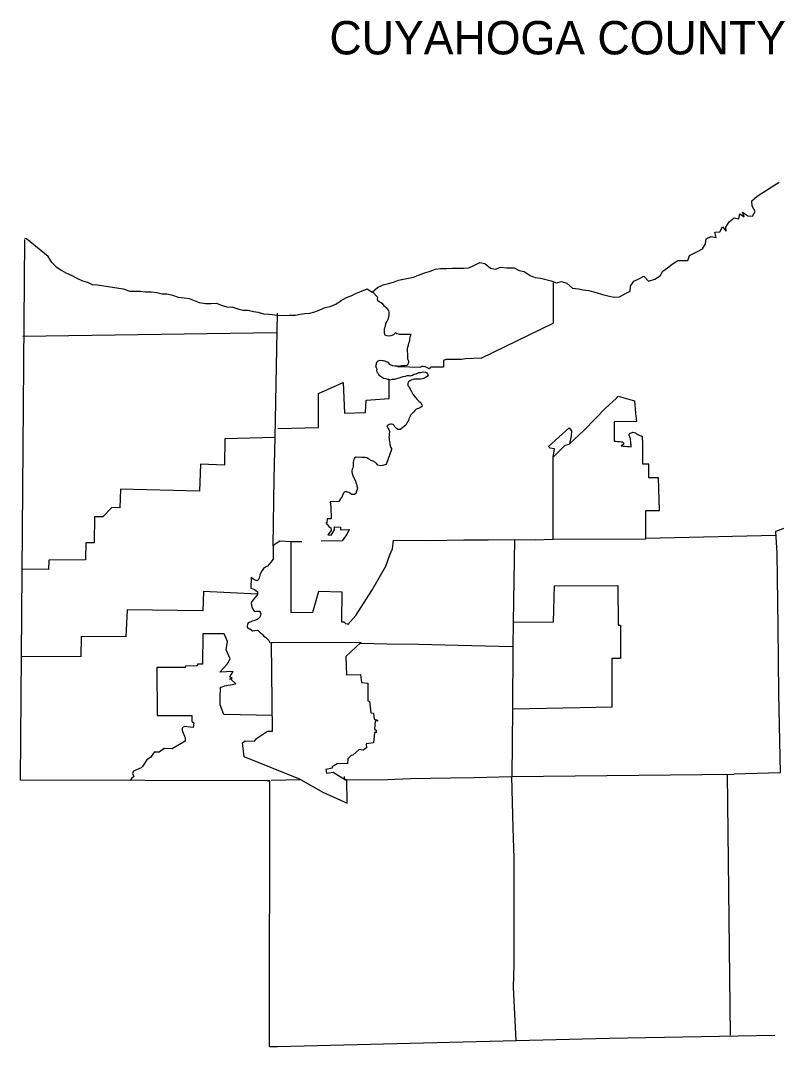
# Model space of a CAD drawing. Extents: x 0 to 42.4, y 0 to 22.
# Drawn here: x 35.55 to 38.719, y 8.263 to 12.563 of the extents above; entities that cross this region are included whole.
import ezdxf

# ---------------------------------------------------------------- set-up
doc = ezdxf.new("R2010")
doc.units = 0
doc.layers.add('Default', color=7, linetype='Continuous')

msp = doc.modelspace()

# ---------------------------------------------------------------- linework, layer by layer
at = {"layer": 'Default'}
for p, q in [((35.55, 9.3795), (35.5675, 11.6444)), ((37.4812, 11.147), (37.7829, 11.2937)), ((38.0562, 10.9878), (38.124, 10.9686)), ((37.833, 10.7825), (37.7837, 10.7319)), ((36.5953, 9.3761), (35.55, 9.3795)), ((36.594, 8.2627), (36.5953, 9.3761))]:
    msp.add_line(p, q, dxfattribs=at)
for points in [[(38.3887, 11.5947), (38.4088, 11.6057), (38.4221, 11.626), (38.4243, 11.6475), (38.4455, 11.6573), (38.4663, 11.6535), (38.4615, 11.675), (38.4821, 11.6773), (38.4937, 11.6981), (38.5078, 11.6792), (38.5073, 11.6969), (38.5203, 11.7186), (38.5415, 11.7355), (38.5622, 11.7317), (38.5651, 11.7518), (38.5837, 11.7394), (38.5764, 11.7599), (38.5997, 11.7444), (38.6193, 11.7427), (38.6305, 11.7625), (38.6178, 11.7838), (38.6159, 11.8067), (38.6388, 11.826), (38.662, 11.8418), (38.6847, 11.8551), (38.7088, 11.8714), (38.7308, 11.8847)], [(35.666, 11.5733), (35.5744, 11.6475), (35.5686, 11.6494)], [(35.6641, 11.5735), (35.6791, 11.5516), (35.6995, 11.5296), (35.7228, 11.5152), (35.7434, 11.5043), (35.7646, 11.4935), (35.7868, 11.4826), (35.8097, 11.4713), (35.831, 11.4665), (35.851, 11.4566), (35.8722, 11.4554), (35.9804, 11.4375)], [(37.9906, 11.4143), (38.0119, 11.4093), (38.0388, 11.4031), (38.0608, 11.4052), (38.0829, 11.4177), (38.1057, 11.4286), (38.108, 11.4494), (38.1211, 11.4702), (38.1429, 11.48), (38.1634, 11.4907), (38.1832, 11.4708), (38.209, 11.4782), (38.2312, 11.4926), (38.2426, 11.5124), (38.2627, 11.5265), (38.2827, 11.5417), (38.3062, 11.5568), (38.3257, 11.5568), (38.3472, 11.5565), (38.355, 11.5773), (38.3887, 11.5947), (38.3887, 11.5947)], [(36.6045, 11.331), (36.6272, 11.3283), (36.6504, 11.3267), (36.6768, 11.3283), (36.7029, 11.3283), (36.7224, 11.3315), (36.7416, 11.3351), (36.7628, 11.3357), (36.7833, 11.3422), (36.8053, 11.3499), (36.8273, 11.3592), (36.8487, 11.3639), (36.8721, 11.374), (36.8945, 11.3885), (36.9163, 11.4012), (36.9384, 11.4102), (36.9587, 11.4195), (36.9793, 11.4277), (37.0031, 11.4384), (37.0239, 11.4246), (37.047, 11.4432), (37.0698, 11.4541), (37.0929, 11.4603), (37.1142, 11.4656), (37.1352, 11.4737), (37.1557, 11.4782), (37.1765, 11.4825), (37.1981, 11.4868), (37.2192, 11.4952), (37.2414, 11.5041), (37.2671, 11.5127), (37.2905, 11.5205), (37.3111, 11.5234), (37.3363, 11.5234), (37.3598, 11.5253), (37.3831, 11.5253), (37.408, 11.5253), (37.4301, 11.526), (37.45, 11.5365), (37.4755, 11.5485), (37.497, 11.5446), (37.5204, 11.5246), (37.5416, 11.5198), (37.5626, 11.5293), (37.5893, 11.526), (37.6199, 11.5262), (37.6405, 11.5153), (37.6619, 11.5103), (37.6865, 11.4945), (37.7077, 11.4849), (37.7306, 11.4825), (37.7524, 11.4768), (37.775, 11.4714), (37.7973, 11.463), (37.8183, 11.4687), (37.84, 11.4618), (37.8646, 11.4403), (37.8887, 11.4379), (37.9089, 11.4336), (37.9319, 11.4315), (37.9631, 11.4233), (37.9906, 11.4143)], [(37.7829, 11.463), (37.7829, 11.2937)], [(35.9804, 11.4375), (35.9839, 11.4367), (36.0085, 11.4286), (36.0314, 11.4286), (36.0527, 11.4277), (36.0735, 11.426), (36.098, 11.4257), (36.1212, 11.4233), (36.1432, 11.4177), (36.1635, 11.4177), (36.1869, 11.4112), (36.211, 11.4031), (36.2365, 11.4009), (36.2573, 11.3974), (36.2776, 11.3885), (36.299, 11.3807), (36.3251, 11.3763), (36.3477, 11.3771), (36.3716, 11.378), (36.3916, 11.3699), (36.4146, 11.362), (36.4396, 11.3613), (36.4608, 11.3549), (36.4838, 11.3491), (36.505, 11.3492), (36.5265, 11.3437), (36.547, 11.34), (36.569, 11.3338), (36.5904, 11.3315), (36.6045, 11.331)], [(37.1304, 11.1138), (37.1406, 11.1152), (37.1478, 11.1164), (37.155, 11.1164), (37.1631, 11.1162), (37.1693, 11.1181), (37.1738, 11.1216), (37.1765, 11.126), (37.1776, 11.1298), (37.1778, 11.1331), (37.1764, 11.1379), (37.1743, 11.1439), (37.1741, 11.1493), (37.1745, 11.1561), (37.1741, 11.1634), (37.1731, 11.179), (37.1731, 11.187), (37.1741, 11.194), (37.1764, 11.2016), (37.1783, 11.2116), (37.1815, 11.2205), (37.1821, 11.2272), (37.1836, 11.2355), (37.1853, 11.2415), (37.1874, 11.2465), (37.155, 11.2465), (37.1395, 11.2465), (37.128, 11.2496), (37.1216, 11.253), (37.1137, 11.2453), (37.1024, 11.2413), (37.0953, 11.2401), (37.0864, 11.241), (37.0788, 11.2443), (37.0753, 11.2524), (37.0753, 11.2598), (37.0755, 11.2689), (37.0769, 11.2754), (37.0797, 11.2818), (37.0814, 11.2925), (37.0853, 11.3004), (37.091, 11.3105), (37.0939, 11.3202), (37.0953, 11.331), (37.096, 11.3393), (37.0936, 11.3468), (37.0869, 11.3551), (37.0815, 11.3597), (37.0753, 11.3649), (37.0705, 11.3725), (37.0616, 11.379), (37.0535, 11.3842), (37.0487, 11.3878), (37.047, 11.3931), (37.048, 11.4014), (37.0263, 11.426)], [(36.6172, 10.8149), (36.6268, 11.3367)], [(36.6236, 11.2541), (35.5598, 11.2382)], [(37.4812, 11.147), (37.4161, 11.1444), (37.3991, 11.1419), (37.3419, 11.1424), (37.3326, 11.1419), (37.3232, 11.1379), (37.3232, 11.1097), (37.269, 11.1097), (37.2636, 11.1024), (37.2538, 11.108), (37.2462, 11.1107), (37.2375, 11.1121), (37.2323, 11.1121), (37.2247, 11.1081), (37.1371, 11.1107), (37.133, 11.1107), (37.1304, 11.1138), (37.1198, 11.1138), (37.1106, 11.1147), (37.1036, 11.1179), (37.0986, 11.1203), (37.0936, 11.1259), (37.0872, 11.1303), (37.0784, 11.1346), (37.0719, 11.1357), (37.0671, 11.1364), (37.0599, 11.1376), (37.0521, 11.1369), (37.048, 11.1346), (37.0445, 11.13), (37.0411, 11.1259), (37.0408, 11.1216), (37.0402, 11.1164), (37.0383, 11.1124), (37.0404, 11.1088), (37.043, 11.1055), (37.0432, 11.1004), (37.043, 11.0956), (37.0437, 11.0902), (37.0461, 11.0871), (37.048, 11.0839), (37.0506, 11.0796), (37.0535, 11.0746), (37.0578, 11.073), (37.0669, 11.0684), (37.0717, 11.0639), (37.0815, 11.0617), (37.0905, 11.0592), (37.0932, 11.0589), (37.101, 11.0567), (37.1101, 11.0589), (37.1191, 11.0598), (37.1275, 11.062), (37.137, 11.0648), (37.1464, 11.0684), (37.1549, 11.0701), (37.164, 11.0727), (37.1717, 11.0746), (37.1796, 11.0746), (37.1843, 11.0734), (37.1927, 11.0763), (37.1993, 11.0801), (37.2082, 11.0818), (37.2146, 11.0839), (37.2196, 11.0871), (37.2247, 11.0878), (37.2285, 11.0878), (37.2337, 11.0887), (37.2409, 11.0902), (37.2476, 11.0887), (37.253, 11.0861), (37.2566, 11.0818), (37.2586, 11.0763), (37.2566, 11.0715), (37.2507, 11.0672), (37.2437, 11.0639), (37.2356, 11.0613), (37.227, 11.0594), (37.2192, 11.0598), (37.2113, 11.0594), (37.202, 11.0591), (37.1946, 11.0584), (37.1876, 11.0553), (37.1821, 11.0518), (37.175, 11.0469), (37.1745, 11.0412), (37.1745, 11.0333), (37.1796, 11.0272), (37.1836, 11.0171), (37.1895, 11.0078), (37.1951, 10.9963), (37.2039, 10.9847), (37.2142, 10.9722)], [(36.6291, 10.8529), (36.7986, 10.8567), (36.7986, 10.9999), (36.9027, 11.046), (36.9079, 10.9169), (36.9964, 10.92), (36.9988, 10.9716), (37.096, 10.9784), (37.0957, 11.0584)], [(37.2142, 10.9722), (37.2213, 10.9661), (37.2256, 10.963), (37.2302, 10.9574), (37.233, 10.9522), (37.2333, 10.9469), (37.2309, 10.9431), (37.2273, 10.94), (37.2222, 10.9384), (37.2179, 10.9371), (37.2129, 10.9355), (37.2077, 10.9322), (37.2032, 10.9281), (37.1987, 10.9221), (37.1865, 10.9095), (37.1815, 10.9016), (37.1783, 10.8927), (37.1771, 10.8853), (37.1731, 10.8803), (37.1693, 10.8744), (37.165, 10.867), (37.1599, 10.8618), (37.1518, 10.8555), (37.1473, 10.8526), (37.142, 10.8488), (37.1316, 10.8481), (37.1258, 10.8526), (37.1198, 10.8598), (37.1163, 10.8653), (37.1118, 10.8691), (37.1055, 10.8708), (37.101, 10.8708), (37.0953, 10.8692), (37.0907, 10.8667), (37.0864, 10.8634), (37.0886, 10.8579), (37.0917, 10.8529), (37.0943, 10.8481), (37.0974, 10.8396), (37.0962, 10.8293), (37.0957, 10.8219), (37.0943, 10.8168), (37.0957, 10.8128), (37.0957, 10.8051), (37.0969, 10.7983), (37.0977, 10.7902), (37.0984, 10.787), (37.0993, 10.7798), (37.1024, 10.773), (37.1049, 10.7689), (37.1058, 10.7648), (37.0829, 10.7025), (37.0671, 10.6975), (37.059, 10.6966), (37.053, 10.6975), (37.0483, 10.6987), (37.0423, 10.7064), (37.0383, 10.7102), (37.0278, 10.7154), (37.0199, 10.719), (37.0105, 10.7243), (37.002, 10.7295), (36.9946, 10.7316), (36.9816, 10.7314), (36.9683, 10.7328), (36.9611, 10.7317), (36.9552, 10.7319), (36.9504, 10.7278), (36.9468, 10.7231), (36.9466, 10.7178), (36.9449, 10.7097), (36.9452, 10.7021), (36.9452, 10.6937), (36.943, 10.688), (36.9404, 10.6825), (36.939, 10.6768), (36.9396, 10.6717), (36.9408, 10.6638), (36.9439, 10.6555), (36.9495, 10.6433), (36.954, 10.6333), (36.9559, 10.6264), (36.9581, 10.6199), (36.9602, 10.6121), (36.9626, 10.604), (36.9607, 10.5975), (36.959, 10.5896), (36.9552, 10.5806), (36.9504, 10.5767), (36.9445, 10.5763), (36.9378, 10.5767), (36.9311, 10.581), (36.9258, 10.5849), (36.9179, 10.5866), (36.9115, 10.5866), (36.9067, 10.5849), (36.9027, 10.5806), (36.9007, 10.5758), (36.8991, 10.5682), (36.8946, 10.5619), (36.8852, 10.5469)], [(37.833, 10.7825), (37.85, 10.7873), (37.9128, 10.8458), (37.9591, 10.8932), (38.0006, 10.936), (38.0484, 10.9797), (38.0562, 10.9878)], [(38.124, 10.9686), (38.1285, 10.9161), (38.1329, 10.8822)], [(38.1329, 10.8822), (38.0384, 10.8813), (38.0384, 10.7997)], [(38.1329, 10.8808), (38.1329, 10.8822)], [(37.7837, 10.7319), (37.7891, 10.7677), (37.7708, 10.7698), (37.7638, 10.7775), (37.85, 10.8548), (37.8601, 10.8433), (37.8581, 10.8219), (37.8509, 10.7878)], [(36.6096, 10.3607), (36.6134, 10.6433), (36.6172, 10.8149), (36.4067, 10.8094), (36.4048, 10.6994), (36.3043, 10.7033), (36.3, 10.5901), (35.9694, 10.5984), (35.9665, 10.5206), (35.9333, 10.5216), (35.8945, 10.4829), (35.8596, 10.4829), (35.8584, 10.3731), (35.8245, 10.3739), (35.8231, 10.302), (35.6684, 10.3015), (35.6672, 10.2614), (35.5555, 10.2631)], [(38.716, 10.4046), (38.1717, 10.3915), (38.171, 10.5092), (38.2285, 10.5092), (38.2254, 10.6455), (38.1842, 10.6464), (38.1842, 10.7039), (38.1584, 10.7033), (38.1588, 10.7866), (38.157, 10.8185)], [(36.7301, 10.3782), (36.6831, 10.3777), (36.6826, 10.0817), (36.7755, 10.0827), (36.801, 10.1708), (36.8972, 10.1677), (36.8953, 10.0425), (36.906, 10.0419), (36.912, 10.0352), (36.9192, 10.0337), (36.926, 10.0344), (36.9225, 10.0316), (36.9559, 10.0683), (37.0227, 10.1733), (37.0822, 10.2762), (37.0982, 10.3232), (37.1096, 10.3485), (37.1136, 10.3851), (37.2538, 10.3832), (37.3369, 10.3851), (37.4087, 10.3861), (37.4383, 10.3861), (37.5104, 10.3861), (37.6209, 10.3872), (37.7094, 10.3863), (37.7837, 10.3891), (37.7837, 10.7276), (37.7837, 10.7324)], [(38.9086, 10.6027), (38.8072, 10.6027), (38.8069, 10.4765), (38.7675, 10.4646), (38.7969, 10.451), (38.7155, 10.4216)], [(36.8852, 10.5469), (36.8487, 10.5453), (36.8516, 10.5249), (36.852, 10.4734), (36.8353, 10.4737), (36.8347, 10.4567), (36.8306, 10.4567), (36.842, 10.4416), (36.8506, 10.4361), (36.853, 10.4304), (36.8525, 10.425), (36.8477, 10.419), (36.8385, 10.4075), (36.8525, 10.4063), (36.8668, 10.4285), (36.8666, 10.4412), (36.8922, 10.439), (36.8921, 10.428), (36.9277, 10.4299), (36.9177, 10.4083), (36.9125, 10.4015), (36.8983, 10.382), (36.8108, 10.3806)], [(38.7155, 10.4216), (38.7203, 10.3307), (38.7246, 10.0216), (38.7276, 9.7421), (38.7351, 9.4096), (38.5403, 9.4041)], [(36.6831, 10.3777), (36.6365, 10.3806), (36.6219, 10.3705), (36.6096, 10.3607), (36.6098, 10.3049), (36.5988, 10.2925), (36.5922, 10.2837), (36.5859, 10.2757), (36.5764, 10.272), (36.5685, 10.2662), (36.563, 10.2579), (36.5577, 10.2483), (36.553, 10.2399), (36.5515, 10.2309), (36.5489, 10.2226), (36.5463, 10.2177), (36.542, 10.2147), (36.5375, 10.2154), (36.5308, 10.2187), (36.5241, 10.2232), (36.5165, 10.2288), (36.5158, 10.1836), (36.5236, 10.1813), (36.5308, 10.1781), (36.537, 10.1733), (36.5429, 10.1677), (36.5429, 10.1578), (36.5394, 10.1512), (36.5325, 10.1431), (36.525, 10.1349), (36.5196, 10.1276), (36.5165, 10.1209), (36.5196, 10.1048), (36.5236, 10.0961), (36.5275, 10.0901), (36.5332, 10.0857), (36.5394, 10.0869), (36.5463, 10.0874), (36.5515, 10.0869), (36.5558, 10.0808), (36.5577, 10.0758), (36.5556, 10.0683), (36.5515, 10.0609), (36.5463, 10.0547), (36.5391, 10.0505), (36.531, 10.0481), (36.5212, 10.0457), (36.5151, 10.0421), (36.5045, 10.038), (36.5015, 10.0307), (36.5, 10.0235), (36.5034, 10.0165), (36.5093, 10.0137), (36.5131, 10.0137), (36.5167, 10.0089), (36.5224, 10.0046), (36.5317, 10.0063), (36.5415, 10.0073), (36.5468, 10.0065), (36.5496, 10.0034), (36.554, 9.9991), (36.563, 9.9912), (36.5707, 9.9822), (36.5776, 9.9786), (36.5838, 9.9714), (36.5909, 9.9638), (36.595, 9.9559), (36.6021, 9.9547)], [(37.6209, 10.3872), (37.6152, 10.0411), (37.7848, 10.0419), (37.7884, 10.1939), (38.0538, 10.1942), (38.0553, 10.028), (38.0656, 10.0285), (38.065, 9.8893), (38.0295, 9.8893), (38.0295, 9.6843), (37.897, 9.6814), (37.612, 9.6767), (37.6096, 9.3936), (38.5403, 9.4041)], [(37.7837, 10.3891), (38.171, 10.3904)], [(36.5429, 10.1578), (36.3169, 10.1691), (36.3145, 10.0884), (35.9968, 10.0927), (35.9913, 9.9789), (35.8044, 9.9803), (35.8023, 9.8953), (35.5539, 9.8977)], [(37.6152, 10.0411), (37.6142, 9.9382)], [(36.6058, 9.6495), (36.4022, 9.6544), (36.3874, 9.6948), (36.3864, 9.7249), (36.3878, 9.7679), (36.4048, 9.7738), (36.4523, 9.7829), (36.431, 9.8032), (36.4262, 9.802), (36.4368, 9.8056), (36.4282, 9.8115), (36.441, 9.8337), (36.3861, 9.8321), (36.4167, 9.8648), (36.4287, 9.8874), (36.4126, 9.9256), (36.4184, 9.9602), (36.4036, 9.9925), (36.3145, 9.9925), (36.3129, 9.8654), (36.2919, 9.8645), (36.2912, 9.8574), (36.242, 9.8571), (36.2406, 9.8509), (36.1212, 9.8509), (36.1229, 9.6499), (36.2689, 9.6499)], [(36.7239, 9.3816), (36.4883, 9.4764), (36.48, 9.5351), (36.4914, 9.544), (36.5312, 9.5427), (36.5391, 9.5533), (36.585, 9.5847), (36.6058, 9.5843), (36.6021, 9.9547)], [(36.9752, 9.9511), (36.9776, 9.9561), (36.6021, 9.9547), (36.6021, 9.9521)], [(36.9764, 9.9555), (36.9139, 9.8965), (36.9163, 9.8201), (36.9752, 9.8218), (36.9795, 9.7881), (37.0056, 9.7855), (37.0068, 9.7115), (37.0134, 9.7103), (37.0187, 9.6612), (37.0301, 9.6597), (37.0321, 9.6344), (37.0461, 9.6309), (37.0464, 9.6256), (37.0371, 9.628), (37.0335, 9.5927), (37.0411, 9.5878), (37.0413, 9.5788), (37.0337, 9.5785), (37.0303, 9.5358), (36.9988, 9.5313), (37.001, 9.5137), (36.9872, 9.5046), (36.9695, 9.5072), (36.943, 9.4831), (36.9359, 9.4829), (36.9222, 9.468), (36.9215, 9.449), (36.8781, 9.4468), (36.8564, 9.4349), (36.8561, 9.4286), (36.8303, 9.4239), (36.8322, 9.4081), (36.8602, 9.4119), (36.9129, 9.3805)], [(37.6142, 9.9382), (37.3843, 9.9431), (37.2179, 9.9469), (37.0871, 9.949), (36.9752, 9.9511)], [(37.6142, 9.9382), (37.612, 9.6767)], [(36.2689, 9.6499), (36.2683, 9.6256), (36.2771, 9.6192), (36.2744, 9.5998), (36.2609, 9.601), (36.2381, 9.6038), (36.2284, 9.5982), (36.2276, 9.5865), (36.2408, 9.5564), (36.2408, 9.542), (36.1854, 9.5096), (36.1517, 9.511), (36.131, 9.4967), (36.1107, 9.4964), (36.0947, 9.4733), (36.0795, 9.4644), (36.0616, 9.4361), (36.0558, 9.4308), (36.0241, 9.4172), (36.02, 9.4069), (36.0257, 9.394), (36.0157, 9.3852), (36.0093, 9.3769)], [(36.5861, 9.3761), (36.5953, 9.3761)], [(36.6003, 9.3795), (36.7239, 9.3816), (36.8168, 9.3287), (36.9192, 9.2828), (36.9177, 9.3804), (36.9096, 9.3804), (36.9079, 9.3936)], [(36.9129, 9.3805), (37.0888, 9.3817), (37.0886, 9.3816), (37.1852, 9.3852), (37.353, 9.3883), (37.4516, 9.3907), (37.6096, 9.3936)], [(37.6273, 8.288), (37.6166, 8.5097), (37.6194, 8.6061), (37.6194, 8.8685), (37.6194, 9.053), (37.6152, 9.1778), (37.6096, 9.3936)], [(38.5121, 9.4034), (38.5255, 8.3107)], [(36.594, 8.2627), (36.628, 8.2627), (38.0175, 8.2973), (38.7126, 8.3095)]]:
    msp.add_lwpolyline(points, dxfattribs=at)
for points in [[(38.1107, 10.7765), (38.1088, 10.7932), (38.1056, 10.8147), (38.102, 10.8264), (38.1033, 10.8307), (38.1107, 10.8352), (38.1174, 10.8371), (38.1283, 10.834), (38.1407, 10.8264), (38.1536, 10.8209), (38.1572, 10.819)], [(38.0384, 10.7999), (38.0682, 10.7971), (38.0765, 10.7946), (38.0789, 10.7902), (38.078, 10.7873), (38.0751, 10.7841), (38.0705, 10.7825), (38.1107, 10.7765)]]:
    msp.add_spline(points, degree=3, dxfattribs=at)

# ---------------------------------------------------------------- texts
msp.add_text('CUYAHOGA COUNTY', height=0.14, dxfattribs=at).set_placement((36.8452, 12.4205))

doc.saveas('drawing.dxf')
